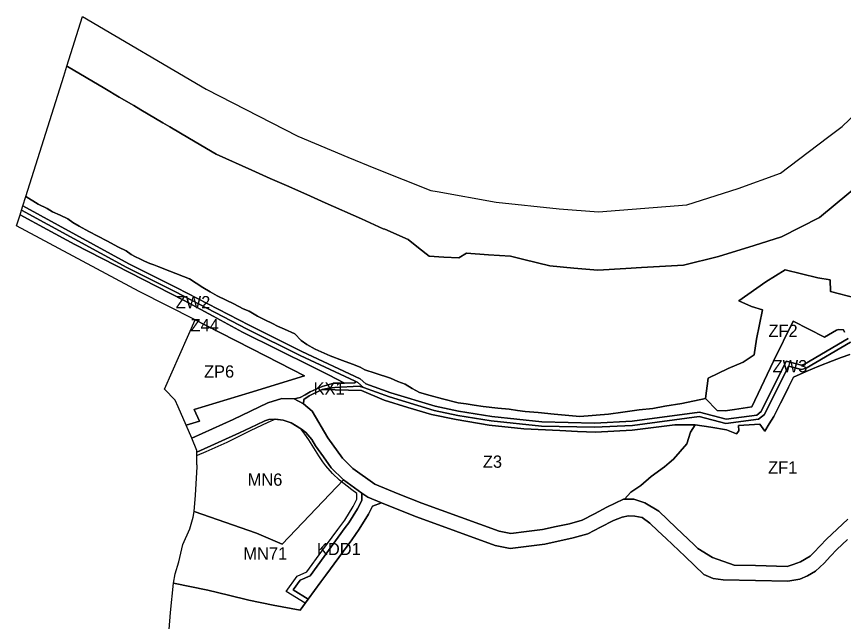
# Model space of a CAD drawing. Extents: x 7428841 to 7433518, y 5545054 to 5546840.
# Drawn here: x 7428841 to 7429514, y 5545546 to 5546039 of the extents above; entities that cross this region are included whole.
import ezdxf

# ---------------------------------------------------------------- set-up
doc = ezdxf.new("R2010")
doc.units = 0
for name, color, linetype in [('linie_rozgraniczajace', 7, 'Continuous'), ('linie_zabudowy_nieprzekraczalne', 7, 'Continuous'), ('oznaczenia_przeznaczen', 7, 'Continuous')]:
    doc.layers.add(name, color=color, linetype=linetype)

msp = doc.modelspace()

# ---------------------------------------------------------------- linework, layer by layer
at = {"layer": 'linie_rozgraniczajace'}
for points in [[(7428881.83, 5545998.54), (7428894.57, 5546038.99), (7428995.18, 5545979.88), (7429069.99, 5545941.58), (7429110.62, 5545924.52), (7429133.22, 5545915.03), (7429178.15, 5545897.27), (7429183.31, 5545896.4), (7429231.48, 5545887.61), (7429282.74, 5545882.27), (7429314.9, 5545879.93), (7429386.68, 5545885.68), (7429428.53, 5545898.75), (7429463.01, 5545911.48), (7429501.36, 5545940.38), (7429513.33, 5545949.4), (7429542.31, 5545977.07)], [(7428848.39, 5545892.29), (7428879.26, 5545990.35), (7428881.83, 5545998.54), (7428882.26, 5545998.26), (7428912.66, 5545980.35), (7428924.48, 5545973.38), (7428936.3, 5545966.42), (7428942.21, 5545962.94), (7428948.11, 5545959.46), (7428959.93, 5545952.5), (7428965.78, 5545949.05), (7428981.63, 5545939.72), (7429003.32, 5545926.93), (7429032.45, 5545913.73), (7429047.52, 5545907.12), (7429060.73, 5545901.24), (7429077.42, 5545893.91), (7429092.24, 5545887.31), (7429121.88, 5545874.1), (7429139.42, 5545866.04), (7429140.79, 5545865.67), (7429159.7, 5545857.25), (7429168.25, 5545850.48), (7429176.81, 5545843.72), (7429188.97, 5545842.98), (7429201.13, 5545842.24), (7429207.44, 5545846.09), (7429225.31, 5545844.9), (7429243.19, 5545843.71), (7429253.92, 5545841.09), (7429275.1, 5545835.91), (7429294.68, 5545834.08), (7429304.46, 5545833.16), (7429314.25, 5545832.24), (7429337.17, 5545833.65), (7429349.94, 5545834.43), (7429383.97, 5545836.52), (7429412.64, 5545843.41), (7429441.7, 5545852.39), (7429463.78, 5545859.4), (7429494.94, 5545875.35), (7429540.93, 5545913.47)], [(7429225.31, 5545844.9), (7429207.44, 5545846.09), (7429201.13, 5545842.24), (7429188.97, 5545842.98), (7429176.81, 5545843.72), (7429168.25, 5545850.48), (7429159.7, 5545857.25), (7429140.79, 5545865.67), (7429139.42, 5545866.04), (7429121.88, 5545874.1), (7429092.24, 5545887.31), (7429077.42, 5545893.91), (7429060.73, 5545901.24), (7429047.52, 5545907.12), (7429032.45, 5545913.73), (7429003.32, 5545926.93), (7428981.63, 5545939.72), (7428965.78, 5545949.05), (7428959.93, 5545952.5), (7428948.11, 5545959.46), (7428942.21, 5545962.94), (7428936.3, 5545966.42), (7428924.48, 5545973.38), (7428912.66, 5545980.35), (7428882.26, 5545998.26), (7428881.83, 5545998.54)], [(7429540.93, 5545913.47), (7429494.94, 5545875.35), (7429463.78, 5545859.4), (7429441.7, 5545852.39), (7429412.64, 5545843.41), (7429383.97, 5545836.52), (7429349.94, 5545834.43), (7429337.17, 5545833.65), (7429314.25, 5545832.24), (7429304.46, 5545833.16), (7429294.68, 5545834.08), (7429275.1, 5545835.91), (7429253.92, 5545841.09), (7429243.19, 5545843.71), (7429225.31, 5545844.9)], [(7428845.99, 5545884.67), (7428848.39, 5545892.29), (7428858.51, 5545886.07), (7428865.68, 5545882.65), (7428870.14, 5545879.92), (7428876.37, 5545877.02), (7428882.59, 5545874.11), (7428886.76, 5545871.22), (7428892.01, 5545868.22), (7428899.83, 5545863.88), (7428914.39, 5545856.1), (7428923.86, 5545851.17), (7428930.15, 5545847.99), (7428934.24, 5545845.11), (7428937.82, 5545843.32), (7428941.4, 5545841.52), (7428944.97, 5545839.73), (7428949.4, 5545837.83), (7428952.64, 5545836.54), (7428956.63, 5545835.03), (7428965.74, 5545831.59), (7428981.8, 5545825.19), (7428992.67, 5545818.18), (7428998.54, 5545814.6), (7429004.26, 5545811.38), (7429011.7, 5545807.81), (7429017.76, 5545804.98), (7429025.43, 5545800.74), (7429030.24, 5545798.79), (7429037.08, 5545794.9), (7429043.22, 5545791.93), (7429049.36, 5545788.95), (7429053.29, 5545786.61), (7429058.99, 5545784.17), (7429067.42, 5545780.57), (7429072.56, 5545775.06), (7429077.23, 5545771.71), (7429084.16, 5545767.99), (7429096.33, 5545762.47), (7429106.31, 5545758.85), (7429114.58, 5545755.6), (7429120.78, 5545753.16), (7429124.41, 5545751.08), (7429133.05, 5545748.36), (7429145.48, 5545744.4), (7429151.43, 5545741.61), (7429157.46, 5545739.36), (7429163.19, 5545736.04), (7429168.92, 5545732.71), (7429177.82, 5545730.21), (7429187.83, 5545727.44), (7429200.49, 5545724.22), (7429207.03, 5545723.39), (7429213.62, 5545722.31), (7429220.93, 5545721.18), (7429232.94, 5545719.86), (7429241.99, 5545719), (7429248.95, 5545717.87), (7429255.05, 5545717.16), (7429265.66, 5545716.33), (7429278.67, 5545715.12), (7429299.53, 5545713.16), (7429322.91, 5545714.93), (7429334.59, 5545716.52), (7429347.88, 5545718.46), (7429359.12, 5545719.74), (7429368.97, 5545721.57), (7429382.62, 5545723.79), (7429402.07, 5545727.72), (7429411.6, 5545718.08), (7429418.11, 5545717.71), (7429425.49, 5545718.8), (7429439.67, 5545720.88), (7429457.44, 5545758.11), (7429473.25, 5545790.66), (7429498.85, 5545777.77), (7429508.64, 5545783.56), (7429510.26, 5545783.96), (7429514.31, 5545783.59), (7429515.27, 5545781.89)], [(7429382.62, 5545723.79), (7429368.97, 5545721.57), (7429359.12, 5545719.74), (7429347.88, 5545718.46), (7429334.59, 5545716.52), (7429322.91, 5545714.93), (7429299.53, 5545713.16), (7429278.67, 5545715.12), (7429265.66, 5545716.33), (7429255.05, 5545717.16), (7429248.95, 5545717.87), (7429241.99, 5545719), (7429232.94, 5545719.86), (7429220.93, 5545721.18), (7429213.62, 5545722.31), (7429207.03, 5545723.39), (7429200.49, 5545724.22), (7429187.83, 5545727.44), (7429177.82, 5545730.21), (7429168.92, 5545732.71), (7429163.19, 5545736.04), (7429157.46, 5545739.36), (7429151.43, 5545741.61), (7429145.48, 5545744.4), (7429133.05, 5545748.36), (7429124.41, 5545751.08), (7429120.78, 5545753.16), (7429114.58, 5545755.6), (7429106.31, 5545758.85), (7429096.33, 5545762.47), (7429084.16, 5545767.99), (7429077.23, 5545771.71), (7429072.56, 5545775.06), (7429067.42, 5545780.57), (7429058.99, 5545784.17), (7429053.29, 5545786.61), (7429049.36, 5545788.95), (7429043.22, 5545791.93), (7429037.08, 5545794.9), (7429030.24, 5545798.79), (7429025.43, 5545800.74), (7429017.76, 5545804.98), (7429011.7, 5545807.81), (7429004.26, 5545811.38), (7428998.54, 5545814.6), (7428992.67, 5545818.18), (7428981.8, 5545825.19), (7428965.74, 5545831.59), (7428956.63, 5545835.03), (7428952.64, 5545836.54), (7428949.4, 5545837.83), (7428944.97, 5545839.73), (7428941.4, 5545841.52), (7428937.82, 5545843.32), (7428934.24, 5545845.11), (7428930.15, 5545847.99), (7428923.86, 5545851.17), (7428914.39, 5545856.1), (7428899.83, 5545863.88), (7428892.01, 5545868.22), (7428886.76, 5545871.22), (7428882.59, 5545874.11), (7428876.37, 5545877.02), (7428870.14, 5545879.92), (7428865.68, 5545882.65), (7428858.51, 5545886.07), (7428848.39, 5545892.29)], [(7428844.92, 5545881.26), (7428845.99, 5545884.67), (7428932.32, 5545837.61), (7428971.31, 5545818.01), (7429030.24, 5545787.44), (7429073.26, 5545766.07), (7429120.7, 5545743.87), (7429125.3, 5545739.83), (7429145.8, 5545732.37), (7429181.92, 5545721.49), (7429200.81, 5545717.32), (7429227.97, 5545713.13), (7429268.72, 5545708.68), (7429311.55, 5545707.77), (7429342.31, 5545709.36), (7429396.97, 5545716.53), (7429418.7, 5545711.05), (7429443.76, 5545714.31), (7429447.35, 5545717.08), (7429467.81, 5545758.16), (7429480.22, 5545754.99), (7429482.58, 5545755.61), (7429518.17, 5545776.56)], [(7429518.17, 5545776.56), (7429482.58, 5545755.61), (7429480.22, 5545754.99), (7429467.81, 5545758.16), (7429447.35, 5545717.08), (7429443.76, 5545714.31), (7429418.7, 5545711.05), (7429396.97, 5545716.53), (7429342.31, 5545709.36), (7429311.55, 5545707.77), (7429268.72, 5545708.68), (7429227.97, 5545713.13), (7429200.81, 5545717.32), (7429181.92, 5545721.49), (7429145.8, 5545732.37), (7429125.3, 5545739.83), (7429120.7, 5545743.87), (7429073.26, 5545766.07), (7429030.24, 5545787.44), (7428971.31, 5545818.01), (7428932.32, 5545837.61), (7428845.99, 5545884.67)], [(7429268.49, 5545705.18), (7429227.51, 5545709.66), (7429200.17, 5545713.88), (7429181.03, 5545718.1), (7429144.69, 5545729.04), (7429123.48, 5545736.76), (7429118.76, 5545740.91), (7429116.73, 5545741.86), (7429071.74, 5545762.92), (7429028.66, 5545784.32), (7428969.72, 5545814.89), (7428930.69, 5545834.5), (7428844.92, 5545881.26)], [(7429545.46, 5545804.09), (7429503.66, 5545814.98), (7429503.45, 5545824.56), (7429493.37, 5545826.12), (7429466.99, 5545832.57), (7429451.21, 5545822.91), (7429429.09, 5545807.46), (7429439.33, 5545802.79), (7429448.43, 5545799.94), (7429443.39, 5545776.05), (7429441.58, 5545763.34), (7429432.62, 5545757.33), (7429420.56, 5545752.22), (7429404.09, 5545744.36), (7429402.07, 5545727.72), (7429382.62, 5545723.79)], [(7429515.27, 5545781.89), (7429514.31, 5545783.59), (7429510.26, 5545783.96), (7429508.64, 5545783.56), (7429498.85, 5545777.77), (7429473.25, 5545790.66), (7429457.44, 5545758.11), (7429439.67, 5545720.88), (7429425.49, 5545718.8), (7429418.11, 5545717.71), (7429411.6, 5545718.08), (7429402.07, 5545727.72), (7429404.09, 5545744.36), (7429420.56, 5545752.22), (7429432.62, 5545757.33), (7429441.58, 5545763.34), (7429443.39, 5545776.05), (7429448.43, 5545799.94), (7429439.33, 5545802.79), (7429429.09, 5545807.46), (7429451.21, 5545822.91), (7429466.99, 5545832.57), (7429493.37, 5545826.12), (7429503.45, 5545824.56), (7429503.66, 5545814.98), (7429545.46, 5545804.09)], [(7429519.61, 5545763.69), (7429512.51, 5545761.03), (7429505.41, 5545758.37), (7429494.17, 5545754.08), (7429483.89, 5545749.63), (7429473.61, 5545745.17), (7429469.52, 5545736.92), (7429465.44, 5545728.67), (7429463.05, 5545723.88), (7429457.56, 5545713.22), (7429453.96, 5545707.13), (7429450.35, 5545701.04), (7429446.28, 5545706.94), (7429428.97, 5545705.64), (7429429.26, 5545701.42), (7429427.15, 5545698.87), (7429419.18, 5545702.34), (7429406.44, 5545704.38), (7429393.69, 5545706.42), (7429376.94, 5545706.43), (7429359.58, 5545704.17), (7429342.23, 5545701.9), (7429327.33, 5545701.06), (7429312.43, 5545700.22), (7429297.84, 5545700.93), (7429283.25, 5545701.63), (7429254.06, 5545703.04), (7429225.91, 5545705.99), (7429198.8, 5545710.67), (7429178.89, 5545714.72), (7429159.59, 5545720.55), (7429140.29, 5545726.38), (7429121.93, 5545734.27), (7429089.8, 5545735.04), (7429093.8, 5545735.92), (7429100.2, 5545736.84), (7429119.8, 5545737.72), (7429123.48, 5545736.76), (7429144.69, 5545729.04), (7429181.03, 5545718.1), (7429200.17, 5545713.88), (7429227.51, 5545709.66), (7429268.49, 5545705.18), (7429311.6, 5545704.27), (7429342.62, 5545705.87), (7429396.77, 5545712.98), (7429418.49, 5545707.5), (7429445.15, 5545710.97), (7429450.13, 5545714.8), (7429469.68, 5545754.07), (7429480.23, 5545751.37), (7429483.94, 5545752.35), (7429520.11, 5545773.64)], [(7429520.11, 5545773.64), (7429483.94, 5545752.35), (7429480.23, 5545751.37), (7429469.68, 5545754.07), (7429450.13, 5545714.8), (7429445.15, 5545710.97), (7429418.49, 5545707.5), (7429396.77, 5545712.98), (7429342.62, 5545705.87), (7429311.6, 5545704.27), (7429268.49, 5545705.18)], [(7429517.79, 5545629.38), (7429509.13, 5545621.31), (7429500.46, 5545613.23), (7429495.29, 5545607.72), (7429490.11, 5545602.21), (7429487.13, 5545599.41), (7429479.26, 5545594.8), (7429473.38, 5545592.57), (7429468.36, 5545591), (7429442.82, 5545591.56), (7429425.27, 5545591.94), (7429407.7, 5545598.17), (7429395.82, 5545605.65), (7429392.81, 5545608.52), (7429378.17, 5545622.49), (7429363.97, 5545635.84), (7429352.61, 5545642.81), (7429343.67, 5545645.6), (7429336.04, 5545645.77), (7429341.28, 5545651.52), (7429349.39, 5545656.78), (7429357.64, 5545664.29), (7429368.62, 5545672.13), (7429372.27, 5545675.29), (7429375.92, 5545678.44), (7429381.36, 5545684.65), (7429386.9, 5545690.84), (7429389.88, 5545700.36), (7429393.69, 5545706.42), (7429406.44, 5545704.38), (7429419.18, 5545702.34), (7429427.15, 5545698.87), (7429429.26, 5545701.42), (7429428.97, 5545705.64), (7429446.28, 5545706.94), (7429450.35, 5545701.04), (7429453.96, 5545707.13), (7429457.56, 5545713.22), (7429463.05, 5545723.88), (7429465.44, 5545728.67), (7429469.52, 5545736.92), (7429473.61, 5545745.17), (7429483.89, 5545749.63), (7429494.17, 5545754.08), (7429505.41, 5545758.37), (7429512.51, 5545761.03), (7429519.61, 5545763.69)], [(7428983.51, 5545695.38), (7429000.46, 5545703.05), (7429017.41, 5545710.71), (7429045.51, 5545724.16), (7429056.98, 5545727.75), (7429066.86, 5545727.38), (7429074.57, 5545723.49), (7429081.63, 5545717.36), (7429094.42, 5545695.79), (7429106.31, 5545679.15), (7429114.87, 5545670.79), (7429132.78, 5545657.86), (7429151.81, 5545650.17), (7429170.84, 5545642.48), (7429202.45, 5545631.04), (7429234.06, 5545619.61), (7429243.37, 5545617.68), (7429256.26, 5545619.34), (7429269.16, 5545621.01), (7429280.23, 5545623.39), (7429291.31, 5545625.76), (7429301.64, 5545628.61), (7429311.57, 5545633.86), (7429321.5, 5545639.11), (7429335.08, 5545645.79), (7429336.04, 5545645.77), (7429343.67, 5545645.6), (7429352.61, 5545642.81), (7429363.97, 5545635.84), (7429378.17, 5545622.49), (7429392.81, 5545608.52), (7429395.82, 5545605.65), (7429407.7, 5545598.17), (7429425.27, 5545591.94), (7429442.82, 5545591.56), (7429468.36, 5545591), (7429473.38, 5545592.57), (7429479.26, 5545594.8), (7429487.13, 5545599.41), (7429490.11, 5545602.21), (7429495.29, 5545607.72), (7429500.46, 5545613.23), (7429509.13, 5545621.31), (7429517.79, 5545629.38)], [(7429146.75, 5545639.27), (7429137.97, 5545642.81), (7429126.94, 5545647.28), (7429122.22, 5545650.69), (7429107.12, 5545661.59), (7429097.16, 5545671.31), (7429090.76, 5545680.27), (7429084.36, 5545689.22), (7429081.34, 5545694.31), (7429076.53, 5545699.96), (7429072.99, 5545702.76), (7429064.41, 5545707.97), (7429057.95, 5545710.18), (7429051.16, 5545710.97), (7429046.41, 5545710.6), (7429043.06, 5545709.68), (7429036.19, 5545706.4), (7429022.47, 5545699.83), (7429005.1, 5545691.98), (7428987.74, 5545684.14), (7428987.8, 5545685.39), (7428983.51, 5545695.38)], [(7428963.09, 5545511.74), (7428966.37, 5545553.5), (7428968.73, 5545577.31), (7428996.69, 5545571.59), (7429013.43, 5545567.46), (7429030.17, 5545563.34), (7429049.92, 5545559.32), (7429071.82, 5545555.21), (7429078.38, 5545564.19), (7429088.8, 5545578.45), (7429092.8, 5545583.92), (7429113.84, 5545612.72), (7429116.91, 5545616.94), (7429119.99, 5545621.16), (7429127.57, 5545633.43), (7429130.75, 5545639.96), (7429137.97, 5545642.81), (7429146.75, 5545639.27), (7429166.55, 5545631.27), (7429198.67, 5545619.65), (7429230.78, 5545608.04), (7429242.9, 5545605.52), (7429271.19, 5545609.17), (7429294.16, 5545614.1), (7429306.09, 5545617.39), (7429316.52, 5545622.91), (7429326.95, 5545628.42), (7429333.99, 5545631.13), (7429339.31, 5545632.02), (7429344.3, 5545631.87), (7429350.33, 5545630.82), (7429356.65, 5545626.26), (7429363.28, 5545620.02), (7429369.92, 5545613.78), (7429385.3, 5545599.1), (7429400.68, 5545584.43), (7429408.18, 5545581.09), (7429416.46, 5545580.13), (7429442.81, 5545579.55), (7429469.16, 5545578.98), (7429478.68, 5545580.46), (7429485.18, 5545583.16), (7429491.47, 5545587.02), (7429498.6, 5545593.72), (7429503.77, 5545599.22), (7429508.94, 5545604.73), (7429517.67, 5545612.86)], [(7429517.67, 5545612.86), (7429508.94, 5545604.73), (7429503.77, 5545599.22), (7429498.6, 5545593.72), (7429491.47, 5545587.02), (7429485.18, 5545583.16), (7429478.68, 5545580.46), (7429469.16, 5545578.98), (7429442.81, 5545579.55), (7429416.46, 5545580.13), (7429408.18, 5545581.09), (7429400.68, 5545584.43), (7429385.3, 5545599.1), (7429369.92, 5545613.78), (7429363.28, 5545620.02), (7429356.65, 5545626.26), (7429350.33, 5545630.82), (7429344.3, 5545631.87), (7429339.31, 5545632.02), (7429333.99, 5545631.13), (7429326.95, 5545628.42), (7429316.52, 5545622.91), (7429306.09, 5545617.39), (7429294.16, 5545614.1), (7429271.19, 5545609.17), (7429242.9, 5545605.52), (7429230.78, 5545608.04), (7429198.67, 5545619.65), (7429166.55, 5545631.27), (7429146.75, 5545639.27)]]:
    msp.add_lwpolyline(points, dxfattribs=at)
for points in [[(7428840.87, 5545868.41), (7428843.71, 5545877.42), (7428865.82, 5545865.35), (7428888.25, 5545853.11), (7428932.75, 5545830.35), (7428977.26, 5545807.58), (7429001.01, 5545794.76), (7429024.77, 5545781.93), (7429053.32, 5545767.69), (7429081.87, 5545753.45), (7429094.96, 5545746.91), (7429108.06, 5545740.38), (7429099.36, 5545740.19), (7429089.71, 5545737.63), (7429079.92, 5545733.13), (7429075.85, 5545730.86), (7429071.77, 5545728.59), (7429066.86, 5545727.38), (7429056.98, 5545727.75), (7429045.51, 5545724.16), (7429017.41, 5545710.71), (7429000.46, 5545703.05), (7428983.51, 5545695.38), (7428978.94, 5545706.02), (7428989.76, 5545709.39), (7428985.46, 5545718.67), (7429030.37, 5545732.46), (7429075.29, 5545746.26), (7429044.16, 5545762.21), (7428994.74, 5545787.46), (7428986.42, 5545791.75), (7428940.78, 5545814.81)], [(7428843.71, 5545877.42), (7428844.92, 5545881.26), (7428930.69, 5545834.5), (7428969.72, 5545814.89), (7429028.66, 5545784.32), (7429071.74, 5545762.92), (7429116.73, 5545741.86), (7429116.76, 5545740.56), (7429108.06, 5545740.38), (7429094.96, 5545746.91), (7429081.87, 5545753.45), (7429053.32, 5545767.69), (7429024.77, 5545781.93), (7429001.01, 5545794.76), (7428977.26, 5545807.58), (7428932.75, 5545830.35), (7428888.25, 5545853.11), (7428865.82, 5545865.35)], [(7428961.5, 5545735.33), (7428986.42, 5545791.75), (7428994.74, 5545787.46), (7429044.16, 5545762.21), (7429075.29, 5545746.26), (7429030.37, 5545732.46), (7428985.46, 5545718.67), (7428989.76, 5545709.39), (7428978.94, 5545706.02), (7428972.46, 5545720.85), (7428969.99, 5545726.39)], [(7429066.86, 5545727.38), (7429071.77, 5545728.59), (7429075.85, 5545730.86), (7429079.92, 5545733.13), (7429089.71, 5545737.63), (7429099.36, 5545740.19), (7429108.06, 5545740.38), (7429116.76, 5545740.56), (7429116.73, 5545741.86), (7429118.76, 5545740.91), (7429123.48, 5545736.76), (7429119.8, 5545737.72), (7429100.2, 5545736.84), (7429093.8, 5545735.92), (7429089.8, 5545735.04), (7429079.23, 5545730), (7429074.86, 5545727.01), (7429074.57, 5545723.49)], [(7429074.57, 5545723.49), (7429074.86, 5545727.01), (7429079.23, 5545730), (7429089.8, 5545735.04), (7429121.93, 5545734.27), (7429140.29, 5545726.38), (7429159.59, 5545720.55), (7429178.89, 5545714.72), (7429198.8, 5545710.67), (7429225.91, 5545705.99), (7429254.06, 5545703.04), (7429283.25, 5545701.63), (7429297.84, 5545700.93), (7429312.43, 5545700.22), (7429327.33, 5545701.06), (7429342.23, 5545701.9), (7429359.58, 5545704.17), (7429376.94, 5545706.43), (7429393.69, 5545706.42), (7429389.88, 5545700.36), (7429386.9, 5545690.84), (7429381.36, 5545684.65), (7429375.92, 5545678.44), (7429372.27, 5545675.29), (7429368.62, 5545672.13), (7429357.64, 5545664.29), (7429349.39, 5545656.78), (7429341.28, 5545651.52), (7429336.04, 5545645.77), (7429335.08, 5545645.79), (7429321.5, 5545639.11), (7429311.57, 5545633.86), (7429301.64, 5545628.61), (7429291.31, 5545625.76), (7429280.23, 5545623.39), (7429269.16, 5545621.01), (7429256.26, 5545619.34), (7429243.37, 5545617.68), (7429234.06, 5545619.61), (7429202.45, 5545631.04), (7429170.84, 5545642.48), (7429151.81, 5545650.17), (7429132.78, 5545657.86), (7429114.87, 5545670.79), (7429106.31, 5545679.15), (7429094.42, 5545695.79), (7429081.63, 5545717.36)], [(7428985.6, 5545635.82), (7428986.72, 5545648.89), (7428987.93, 5545672.07), (7428988.03, 5545673.23), (7428987.68, 5545673.86), (7428987.59, 5545680.68), (7428987.74, 5545684.14), (7429005.1, 5545691.98), (7429022.47, 5545699.83), (7429036.19, 5545706.4), (7429043.06, 5545709.68), (7429046.41, 5545710.6), (7429051.16, 5545710.97), (7429057.95, 5545710.18), (7429064.41, 5545707.97), (7429072.99, 5545702.76), (7429076.53, 5545699.96), (7429081.34, 5545694.31), (7429084.36, 5545689.22), (7429090.76, 5545680.27), (7429097.16, 5545671.31), (7429107.12, 5545661.59), (7429057.28, 5545609.07), (7429036.39, 5545618.03)], [(7428968.73, 5545577.31), (7428970.04, 5545584.86), (7428972.99, 5545594.76), (7428976.36, 5545608.9), (7428981.93, 5545621.63), (7428984.78, 5545631.18), (7428985.6, 5545635.82), (7429036.39, 5545618.03), (7429057.28, 5545609.07), (7429107.12, 5545661.59), (7429122.22, 5545650.69), (7429122.07, 5545644.65), (7429118.63, 5545637.9), (7429111.49, 5545626.43), (7429108.63, 5545622.53), (7429079.97, 5545583.3), (7429071.96, 5545579.74), (7429066.23, 5545571.75), (7429078.38, 5545564.19), (7429071.82, 5545555.21), (7429049.92, 5545559.32), (7429030.17, 5545563.34), (7429013.43, 5545567.46), (7428996.69, 5545571.59)], [(7429066.23, 5545571.75), (7429071.96, 5545579.74), (7429079.97, 5545583.3), (7429108.63, 5545622.53), (7429111.49, 5545626.43), (7429118.63, 5545637.9), (7429122.07, 5545644.65), (7429122.22, 5545650.69), (7429126.94, 5545647.28), (7429137.97, 5545642.81), (7429130.75, 5545639.96), (7429127.57, 5545633.43), (7429119.99, 5545621.16), (7429116.91, 5545616.94), (7429113.84, 5545612.72), (7429092.8, 5545583.92), (7429088.8, 5545578.45), (7429078.38, 5545564.19)]]:
    msp.add_lwpolyline(points, close=True, dxfattribs=at)
at = {"layer": 'linie_zabudowy_nieprzekraczalne'}
for points in [[(7429072.52, 5545703.05), (7429068.7, 5545705.37), (7429064.41, 5545707.97), (7429057.95, 5545710.18), (7429051.72, 5545710.85), (7429045.44, 5545708.21), (7429031.17, 5545701.28), (7429012.27, 5545692.01), (7428995.17, 5545684.26), (7428987.92, 5545681.44)], [(7429118.12, 5545650.27), (7429113.95, 5545653.23), (7429103.82, 5545661.26), (7429098.24, 5545666.7), (7429092.89, 5545672.86), (7429090.43, 5545676.25), (7429087.08, 5545681.05), (7429078.81, 5545694.18), (7429075.69, 5545698.66), (7429072.52, 5545703.05)], [(7429069.32, 5545582.94), (7429077.37, 5545586.52), (7429089.63, 5545603.32), (7429102.54, 5545620.99), (7429108.18, 5545628.67), (7429115.14, 5545639.87), (7429118.1, 5545645.66), (7429118.12, 5545650.27)], [(7429076.03, 5545560.96), (7429060.52, 5545570.41), (7429069.32, 5545582.94)]]:
    msp.add_lwpolyline(points, dxfattribs=at)

# ---------------------------------------------------------------- texts
at = {"layer": 'oznaczenia_przeznaczen'}
for s, p in [('ZW2', (7428970.46, 5545801.27)), ('Z44', (7428982.55, 5545782.46)), ('ZF2', (7429453.25, 5545777.89)), ('ZW3', (7429456.65, 5545749.07)), ('ZP6', (7428993.57, 5545744.75)), ('KX1', (7429082.81, 5545730.92)), ('Z3', (7429220.67, 5545671.31)), ('ZF1', (7429452.98, 5545666.56)), ('MN6', (7429029.13, 5545656.68)), ('KDD1', (7429085.52, 5545600.15)), ('MN71', (7429025.61, 5545596.43))]:
    msp.add_text(s, height=10, dxfattribs=at).set_placement(p)

doc.saveas('drawing.dxf')
